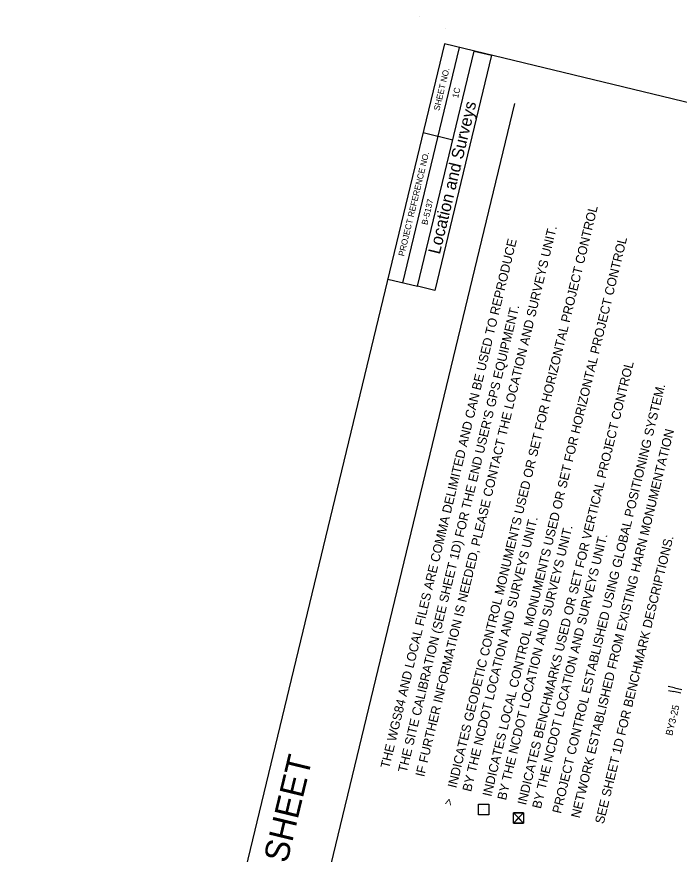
# Model space of a CAD drawing. Extents: x 1649669 to 1659218, y 588594 to 607900.
# Drawn here: x 1649669 to 1653461, y 603109 to 607900 of the extents above; entities that cross this region are included whole.
import ezdxf

# ---------------------------------------------------------------- set-up
doc = ezdxf.new("R2010")
doc.units = 0
for name, color, linetype in [('CTL Bench Mark CELL', 7, 'Continuous'), ('CTL Sheet Border CELL', 7, 'Continuous'), ('CTL Sheet Notes CELL', 7, 'Continuous'), ('CTL Supplemental Horizontal and Vertical CELL', 7, 'Continuous'), ('CTL Supplemental Horizontal and Vertical Text', 7, 'Continuous'), ('Exist Roads EOP', 7, 'Continuous')]:
    doc.layers.add(name, color=color, linetype=linetype)

# ---------------------------------------------------------------- blocks, each defined once
blk = doc.blocks.new('CTL SUPPLEMENTAL HORIZONTAL AND VERTICAL')
at = {"layer": 'CTL Supplemental Horizontal and Vertical CELL'}
blk.add_line((0, 0), (0, 0), dxfattribs=at)
blk.add_lwpolyline([(-0.0735, 0.074), (0.07475, 0.074), (0.07475, -0.0745), (-0.0735, -0.0745)], close=True, dxfattribs=at)
blk = doc.blocks.new('CTL BENCH MARK')
at = {"layer": 'CTL Bench Mark CELL'}
blk.add_line((0, 0), (0, 0), dxfattribs=at)
blk.add_lwpolyline([(-0.072, 0.07175), (0.07175, 0.07175), (0.07175, -0.072), (-0.072, -0.072)], close=True, dxfattribs=at)
for points in [[(0.07175, 0.07175), (-0.072, -0.072), (-0.000125, -0.000125), (0.07175, -0.072), (-0.072, 0.07175)], [(-0.000125, -0.000125), (0.07175, 0.07175), (-0.072, 0.07175), (-0.000125, -0.000125)], [(-0.000125, -0.000125), (-0.072, -0.072), (0.07175, -0.072), (-0.000125, -0.000125)]]:
    blk.add_lwpolyline(points, dxfattribs=at)

msp = doc.modelspace()

# ---------------------------------------------------------------- linework, layer by layer
at = {"layer": 'CTL Sheet Border CELL'}
for p, q in [((1651976.3, 607900.1), (1651976.3, 607900.1)), ((1652120.7, 607833), (1652120.7, 607833)), ((1652120.7, 607833), (1652120.7, 607833)), ((1651877.7, 606378.6), (1652202.5, 607723.8)), ((1651995.4, 607237.1), (1652164.5, 607196.3)), ((1651793.1, 606399.1), (1651962.2, 606358.2))]:
    msp.add_line(p, q, dxfattribs=at)
for points in [[(1652117.6, 607744.3), (1649668.6, 597600.9), (1656768.8, 595886.6), (1659217.9, 606030)], [(1651962.2, 606358.2), (1652286.9, 607703.4), (1652386.5, 607679.4), (1652061.7, 606334.2)]]:
    msp.add_lwpolyline(points, close=True, dxfattribs=at)
at = {"layer": 'CTL Sheet Notes CELL'}
msp.add_line((1650617.4, 599524.6), (1652519.8, 607403.9), dxfattribs=at)
at = {"layer": 'Exist Roads EOP'}
for p, q in [((1653434.3, 604060.7), (1653397.7, 604068.1)), ((1653434.3, 604060.7), (1653475.6, 604051.2)), ((1653399.1, 604045.3), (1653429.2, 604039.1)), ((1653469.8, 604029.9), (1653429.2, 604039.1))]:
    msp.add_line(p, q, dxfattribs=at)

# ---------------------------------------------------------------- block references
at = {"layer": 'CTL Sheet Notes CELL', "xscale": 399.99999999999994, "yscale": 399.9999999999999}
for name, p in [('CTL SUPPLEMENTAL HORIZONTAL AND VERTICAL', (1652340.5, 603364.8)), ('CTL BENCH MARK', (1652540.1, 603316.2))]:
    msp.add_blockref(name, p, dxfattribs=at)

# ---------------------------------------------------------------- texts
at = {"layer": 'CTL Sheet Border CELL'}
for s, height, p in [('SHEET NO.', 34.78, (1652087.8, 607360.1)), ('1C', 34.78, (1652194.6, 607432.3)), ('Location and Surveys', 69.566, (1652090.1, 606537.4)), ('PROJECT REFERENCE NO.', 34.783, (1651886.1, 606527.5)), ('B-5137', 34.78, (1652018.7, 606706.6)), ('SURVEY CONTROL SHEET', 139.13, (1650798.4, 601324.6))]:
    msp.add_text(s, height=height, rotation=76.4261, dxfattribs=at).set_placement(p)
at = {"layer": 'CTL Sheet Notes CELL'}
for s, height, rotation, p in [('INDICATES GEODETIC CONTROL MONUMENTS USED OR SET FOR HORIZONTAL PROJECT CONTROL', 52.174, 76.3208, (1652184.7, 603484.1)), ('IF FURTHER INFORMATION IS NEEDED, PLEASE CONTACT THE LOCATION AND SURVEYS UNIT.', 52.174, 76.4261, (1652000.5, 603548.5)), ('THE WGS84 AND LOCAL FILES ARE COMMA DELIMITED AND CAN BE USED TO REPRODUCE', 52.174, 76.4261, (1651800.7, 603596.7)), ('INDICATES LOCAL CONTROL MONUMENTS USED OR SET FOR HORIZONTAL PROJECT CONTROL', 52.174, 76.3208, (1652384.4, 603435.5)), ("THE SITE CALIBRATION (SEE SHEET 1D) FOR THE END USER'S GPS EQUIPMENT. ", 52.174, 76.4261, (1651900.6, 603572.6)), ('INDICATES BENCHMARKS USED OR SET FOR VERTICAL PROJECT CONTROL', 52.174, 76.3208, (1652584, 603386.9)), ('PROJECT CONTROL ESTABLISHED USING GLOBAL POSITIONING SYSTEM.', 52.174, 76.3208, (1652783.7, 603338.3)), ('NETWORK ESTABLISHED FROM EXISTING HARN MONUMENTATION', 52.174, 76.3208, (1652891, 603312.4)), ('BY THE NCDOT LOCATION AND SURVEYS UNIT.', 52.174, 76.3208, (1652269.1, 603463.3)), ('BY THE NCDOT LOCATION AND SURVEYS UNIT.', 52.174, 76.3208, (1652468.8, 603414.7)), ('BY THE NCDOT LOCATION AND SURVEYS UNIT.', 52.174, 76.3208, (1652668.4, 603366.1)), ('SEE SHEET 1D FOR BENCHMARK DESCRIPTIONS.', 52.174, 76.3208, (1653028.2, 603279.2)), ('>', 48.9, 76.3207, (1652158.8, 603383.9))]:
    msp.add_text(s, height=height, rotation=rotation, dxfattribs=at).set_placement(p)
at = {"layer": 'CTL Supplemental Horizontal and Vertical Text'}
msp.add_text('BY3-25', height=40, rotation=76.4261, dxfattribs=at).set_placement((1653420.6, 603784.1))

doc.saveas('drawing.dxf')
